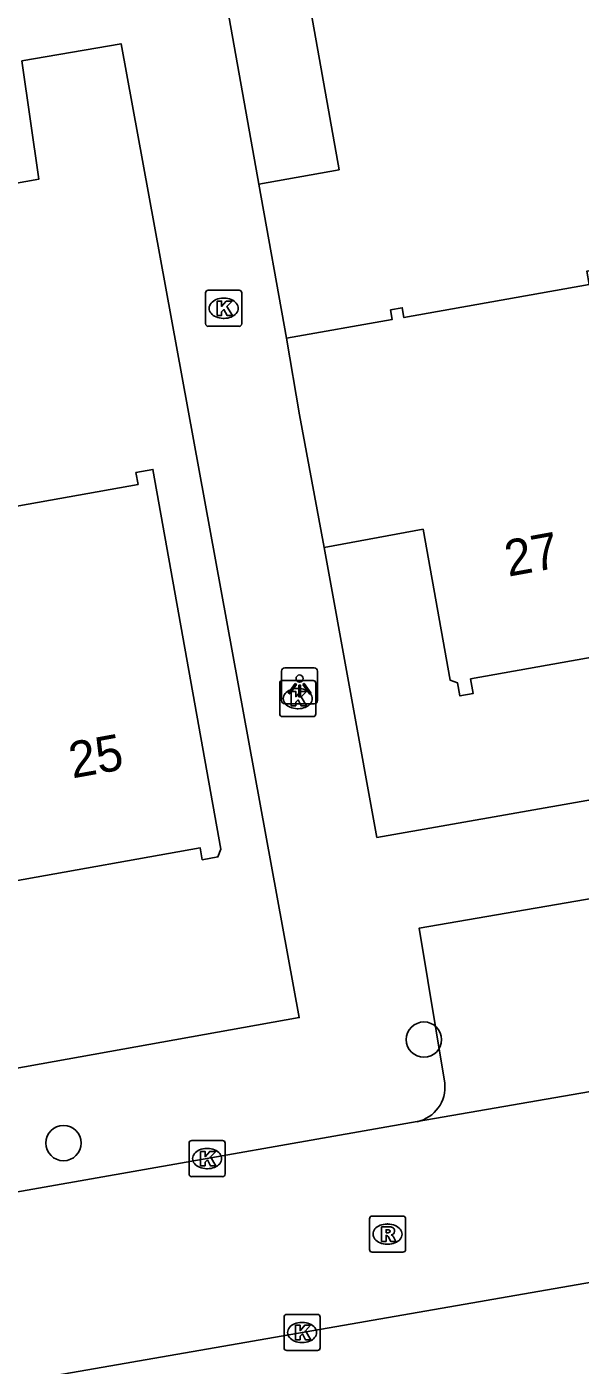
# Model space of a CAD drawing. Extents: x 157793 to 159380, y 380882 to 382313.
# Drawn here: x 158465.8 to 158481.12, y 381373.42 to 381410.46 of the extents above; entities that cross this region are included whole.
import ezdxf

# ---------------------------------------------------------------- set-up
doc = ezdxf.new("R2010")
doc.units = 0
for name, color, linetype in [('IMGEO_Boom', 7, 'Continuous'), ('IMGEO_Kolk', 7, 'Continuous'), ('IMGEO_Lichtpunt', 7, 'Continuous'), ('IMGEO_Pand', 7, 'Continuous'), ('IMGEO_Pand_nummerreeks', 7, 'Continuous'), ('IMGEO_Rijbaan_lokaal_open', 7, 'Continuous'), ('IMGEO_Rioolput', 7, 'Continuous'), ('IMGEO_Voetpad_open', 7, 'Continuous')]:
    doc.layers.add(name, color=color, linetype=linetype)

msp = doc.modelspace()

# ---------------------------------------------------------------- linework, layer by layer
at = {"layer": 'IMGEO_Boom'}
for centre in [(158476.793, 381382.428), (158466.813, 381379.566)]:
    msp.add_circle(centre, 0.489, dxfattribs=at)
at = {"layer": 'IMGEO_Kolk'}
for p, q in [((158470.823, 381403.167), (158471.675, 381403.167)), ((158470.748, 381402.241), (158470.748, 381403.093)), ((158471.236, 381402.947), (158471.261, 381402.947)), ((158471.749, 381403.093), (158471.749, 381402.241)), ((158471.675, 381402.167), (158470.823, 381402.167)), ((158471.259, 381402.387), (158471.234, 381402.387)), ((158472.8, 381391.44), (158472.8, 381392.292)), ((158472.875, 381392.366), (158473.727, 381392.366)), ((158473.288, 381392.146), (158473.313, 381392.146)), ((158473.801, 381392.292), (158473.801, 381391.44)), ((158473.727, 381391.366), (158472.875, 381391.366)), ((158473.311, 381391.586), (158473.286, 381391.586)), ((158470.289, 381378.71), (158470.289, 381379.562)), ((158470.364, 381379.636), (158471.216, 381379.636)), ((158471.29, 381379.562), (158471.29, 381378.71)), ((158470.777, 381379.416), (158470.802, 381379.416)), ((158470.8, 381378.856), (158470.775, 381378.856)), ((158471.216, 381378.636), (158470.364, 381378.636)), ((158472.919, 381373.898), (158472.919, 381374.75)), ((158472.994, 381374.824), (158473.846, 381374.824)), ((158473.92, 381374.75), (158473.92, 381373.898)), ((158473.407, 381374.604), (158473.432, 381374.604)), ((158473.43, 381374.044), (158473.405, 381374.044)), ((158473.846, 381373.824), (158472.994, 381373.824))]:
    msp.add_line(p, q, dxfattribs=at)
for points in [[(158470.823, 381403.167), (158471.675, 381403.167)], [(158470.748, 381402.241), (158470.748, 381403.093)], [(158471.069, 381402.867), (158471.192, 381402.867), (158471.192, 381402.716), (158471.322, 381402.867), (158471.486, 381402.867), (158471.34, 381402.716), (158471.493, 381402.467), (158471.341, 381402.467), (158471.256, 381402.631), (158471.192, 381402.564), (158471.192, 381402.467), (158471.069, 381402.467), (158471.069, 381402.867)], [(158471.749, 381403.093), (158471.749, 381402.241)], [(158471.675, 381402.167), (158470.823, 381402.167)], [(158472.8, 381391.44), (158472.8, 381392.292)], [(158472.875, 381392.366), (158473.727, 381392.366)], [(158473.121, 381392.066), (158473.244, 381392.066), (158473.244, 381391.915), (158473.374, 381392.066), (158473.538, 381392.066), (158473.392, 381391.915), (158473.545, 381391.666), (158473.393, 381391.666), (158473.308, 381391.83), (158473.244, 381391.763), (158473.244, 381391.666), (158473.121, 381391.666), (158473.121, 381392.066)], [(158473.801, 381392.292), (158473.801, 381391.44)], [(158473.727, 381391.366), (158472.875, 381391.366)], [(158470.289, 381378.71), (158470.289, 381379.562)], [(158470.364, 381379.636), (158471.216, 381379.636)], [(158471.29, 381379.562), (158471.29, 381378.71)], [(158470.61, 381379.336), (158470.733, 381379.336), (158470.733, 381379.185), (158470.863, 381379.336), (158471.027, 381379.336), (158470.881, 381379.185), (158471.034, 381378.936), (158470.882, 381378.936), (158470.797, 381379.1), (158470.733, 381379.033), (158470.733, 381378.936), (158470.61, 381378.936), (158470.61, 381379.336)], [(158471.216, 381378.636), (158470.364, 381378.636)], [(158472.919, 381373.898), (158472.919, 381374.75)], [(158472.994, 381374.824), (158473.846, 381374.824)], [(158473.92, 381374.75), (158473.92, 381373.898)], [(158473.24, 381374.524), (158473.363, 381374.524), (158473.363, 381374.373), (158473.493, 381374.524), (158473.657, 381374.524), (158473.511, 381374.373), (158473.664, 381374.124), (158473.512, 381374.124), (158473.427, 381374.288), (158473.363, 381374.221), (158473.363, 381374.124), (158473.24, 381374.124), (158473.24, 381374.524)], [(158473.846, 381373.824), (158472.994, 381373.824)]]:
    msp.add_lwpolyline(points, dxfattribs=at)
for centre, start, end in [((158470.825, 381403.091), 91.552, 178.448), ((158470.825, 381403.091), 91.552, 178.448), ((158471.673, 381403.091), 1.552, 88.448), ((158471.673, 381403.091), 1.552, 88.448), ((158470.825, 381402.243), 181.552, 268.448), ((158470.825, 381402.243), 181.552, 268.448), ((158471.673, 381402.243), 271.552, 358.448), ((158471.673, 381402.243), 271.552, 358.448), ((158472.877, 381392.29), 91.552, 178.448), ((158472.877, 381392.29), 91.552, 178.448), ((158473.725, 381392.29), 1.552, 88.448), ((158473.725, 381392.29), 1.552, 88.448), ((158472.877, 381391.442), 181.552, 268.448), ((158472.877, 381391.442), 181.552, 268.448), ((158473.725, 381391.442), 271.552, 358.448), ((158473.725, 381391.442), 271.552, 358.448), ((158470.366, 381379.56), 91.552, 178.448), ((158470.366, 381379.56), 91.552, 178.448), ((158471.214, 381379.56), 1.552, 88.448), ((158471.214, 381379.56), 1.552, 88.448), ((158470.366, 381378.712), 181.552, 268.448), ((158470.366, 381378.712), 181.552, 268.448), ((158471.214, 381378.712), 271.552, 358.448), ((158471.214, 381378.712), 271.552, 358.448), ((158472.996, 381374.748), 91.552, 178.448), ((158472.996, 381374.748), 91.552, 178.448), ((158473.844, 381374.748), 1.552, 88.448), ((158473.844, 381374.748), 1.552, 88.448), ((158472.996, 381373.9), 181.552, 268.448), ((158472.996, 381373.9), 181.552, 268.448), ((158473.844, 381373.9), 271.552, 358.448), ((158473.844, 381373.9), 271.552, 358.448)]:
    msp.add_arc(centre, 0.0765, start, end, dxfattribs=at)
for centre, major_axis, ratio, start_param, end_param in [((158471.235, 381402.667), (-0.387, 0.002), 0.722429, 4.712389, 7.853982), ((158471.26, 381402.667), (-0.39, 0.002), 0.717154, 1.570796, 4.712389), ((158473.287, 381391.866), (-0.387, 0.002), 0.722429, 4.712389, 7.853982), ((158473.312, 381391.866), (-0.39, 0.002), 0.717154, 1.570796, 4.712389), ((158470.776, 381379.136), (-0.387, 0.002), 0.722429, 4.712389, 7.853982), ((158470.801, 381379.136), (-0.39, 0.002), 0.717154, 1.570796, 4.712389), ((158473.406, 381374.324), (-0.387, 0.002), 0.722429, 4.712389, 7.853982), ((158473.431, 381374.324), (-0.39, 0.002), 0.717154, 1.570796, 4.712389)]:
    msp.add_ellipse(centre, major_axis=major_axis, ratio=ratio, start_param=start_param, end_param=end_param, dxfattribs=at)
at = {"layer": 'IMGEO_Lichtpunt'}
for p, q in [((158472.852, 381392.621), (158472.852, 381391.814)), ((158472.852, 381392.621), (158472.852, 381391.814)), ((158473.754, 381392.716), (158472.946, 381392.716)), ((158473.754, 381392.716), (158472.946, 381392.716)), ((158473.848, 381391.814), (158473.848, 381392.621)), ((158473.848, 381391.814), (158473.848, 381392.621)), ((158472.946, 381391.72), (158473.754, 381391.72)), ((158472.946, 381391.72), (158473.754, 381391.72))]:
    msp.add_line(p, q, dxfattribs=at)
for points in [[(158473.226, 381392.285), (158473.265, 381392.257), (158473.077, 381391.995), (158473.039, 381392.022), (158473.226, 381392.285)], [(158473.328, 381392.237), (158473.375, 381392.237), (158473.375, 381391.915), (158473.328, 381391.915), (158473.328, 381392.237)], [(158473.438, 381392.257), (158473.476, 381392.284), (158473.663, 381392.022), (158473.624, 381391.994), (158473.438, 381392.257)]]:
    msp.add_lwpolyline(points, dxfattribs=at)
msp.add_circle((158473.351, 381392.419), 0.0994, dxfattribs=at)
for centre, start, end in [((158472.946, 381392.621), 90, 180), ((158472.946, 381392.621), 90, 180), ((158473.754, 381392.621), 0, 90), ((158473.754, 381392.621), 0, 90), ((158472.946, 381391.814), 180, 270), ((158472.946, 381391.814), 180, 270), ((158473.754, 381391.814), 270, 0), ((158473.754, 381391.814), 270, 360)]:
    msp.add_arc(centre, 0.0946, start, end, dxfattribs=at)
at = {"layer": 'IMGEO_Pand'}
for points in [[(158472.984, 381414.675), (158474.445, 381406.502), (158472.222, 381406.104)], [(158472.222, 381406.104), (158470.761, 381414.277)], [(158465.655, 381409.513), (158466.13, 381406.238), (158461.953, 381405.491)], [(158472.987, 381401.837), (158475.915, 381402.357), (158475.868, 381402.623), (158476.192, 381402.681), (158476.241, 381402.407), (158481.368, 381403.324), (158481.302, 381403.693), (158481.518, 381403.732)], [(158472.987, 381401.837), (158473.348, 381399.718), (158474.035, 381396.043)], [(158463.395, 381397.123), (158463.601, 381397.16), (158463.655, 381396.858), (158468.877, 381397.792), (158468.818, 381398.121), (158469.29, 381398.205), (158471.168, 381387.698), (158471.091, 381387.485), (158470.656, 381387.407), (158470.598, 381387.732), (158465.439, 381386.809), (158465.506, 381386.433), (158465.333, 381386.402)], [(158483.44, 381393.021), (158483.216, 381392.981), (158483.156, 381393.315), (158478.085, 381392.408), (158478.157, 381392.006), (158477.788, 381391.94), (158477.723, 381392.304), (158477.516, 381392.378), (158476.77, 381396.551), (158474.035, 381396.043)]]:
    msp.add_lwpolyline(points, dxfattribs=at)
at = {"layer": 'IMGEO_Rijbaan_lokaal_open'}
for points in [[(158504.063, 381384.916), (158476.602, 381380.158)], [(158476.602, 381380.158), (158440.528, 381373.814)], [(158488.117, 381376.88), (158452.624, 381370.708)]]:
    msp.add_lwpolyline(points, dxfattribs=at)
at = {"layer": 'IMGEO_Rioolput'}
for p, q in [((158475.285, 381376.62), (158475.285, 381377.472)), ((158475.36, 381377.546), (158476.212, 381377.546)), ((158475.773, 381377.326), (158475.798, 381377.326)), ((158476.286, 381377.472), (158476.286, 381376.62)), ((158476.212, 381376.546), (158475.36, 381376.546)), ((158475.796, 381376.766), (158475.771, 381376.766))]:
    msp.add_line(p, q, dxfattribs=at)
for points in [[(158475.285, 381376.62), (158475.285, 381377.472)], [(158475.36, 381377.546), (158476.212, 381377.546)], [(158475.874, 381377.244), (158475.622, 381377.246), (158475.622, 381376.846)], [(158476.286, 381377.472), (158476.286, 381376.62)], [(158475.622, 381376.846), (158475.746, 381376.846), (158475.746, 381377.008), (158475.757, 381377.008)], [(158475.8, 381377.165), (158475.746, 381377.165), (158475.746, 381377.084)], [(158475.746, 381377.084), (158475.798, 381377.084)], [(158475.804, 381376.979), (158475.875, 381376.846), (158476.015, 381376.846), (158475.95, 381376.972)], [(158476.212, 381376.546), (158475.36, 381376.546)]]:
    msp.add_lwpolyline(points, dxfattribs=at)
for centre, radius, start, end in [((158475.362, 381377.47), 0.0765, 91.552, 178.448), ((158475.362, 381377.47), 0.0765, 91.552, 178.448), ((158475.873, 381377.134), 0.109, 350.3612, 89.416), ((158476.21, 381377.47), 0.0765, 1.552, 88.448), ((158476.21, 381377.47), 0.0765, 1.552, 88.448), ((158475.756, 381376.955), 0.0533, 26.0293, 88.6989), ((158475.782, 381377.273), 0.19, 274.7715, 282.9687), ((158475.806, 381377.069), 0.0964, 77.0061, 93.1865), ((158475.82, 381377.126), 0.0378, 276.6634, 79.6772), ((158475.871, 381377.134), 0.112, 277.5842, 350.9817), ((158475.855, 381376.919), 0.108, 29.5134, 73.7905), ((158475.362, 381376.622), 0.0765, 181.552, 268.448), ((158475.362, 381376.622), 0.0765, 181.552, 268.448), ((158476.21, 381376.622), 0.0765, 271.552, 358.448), ((158476.21, 381376.622), 0.0765, 271.552, 358.448)]:
    msp.add_arc(centre, radius, start, end, dxfattribs=at)
for centre, major_axis, ratio, start_param, end_param in [((158475.772, 381377.046), (-0.387, 0.002), 0.722429, 4.712389, 7.853982), ((158475.797, 381377.046), (-0.39, 0.002), 0.717154, 1.570796, 4.712389)]:
    msp.add_ellipse(centre, major_axis=major_axis, ratio=ratio, start_param=start_param, end_param=end_param, dxfattribs=at)
at = {"layer": 'IMGEO_Voetpad_open'}
for points in [[(158465.655, 381409.513), (158468.406, 381409.988), (158473.339, 381383.038), (158430.261, 381375.309), (158426.84, 381374.689)], [(158472.222, 381406.104), (158472.987, 381401.837)], [(158474.035, 381396.043), (158475.493, 381388.023), (158501.001, 381392.51)], [(158477.371, 381381.22), (158476.663, 381385.514), (158502.313, 381389.933), (158503.047, 381385.672)]]:
    msp.add_lwpolyline(points, dxfattribs=at)
msp.add_arc((158476.399, 381381.114), 0.978, 281.973, 6.21, dxfattribs=at)

# ---------------------------------------------------------------- texts
at = {"layer": 'IMGEO_Pand_nummerreeks'}
for s, rotation, p in [('27', 10.3992, (158479.129, 381395.236)), ('25', 10.2077, (158467.06, 381389.654))]:
    msp.add_text(s, height=1, rotation=rotation, dxfattribs=at).set_placement(p)

doc.saveas('drawing.dxf')
